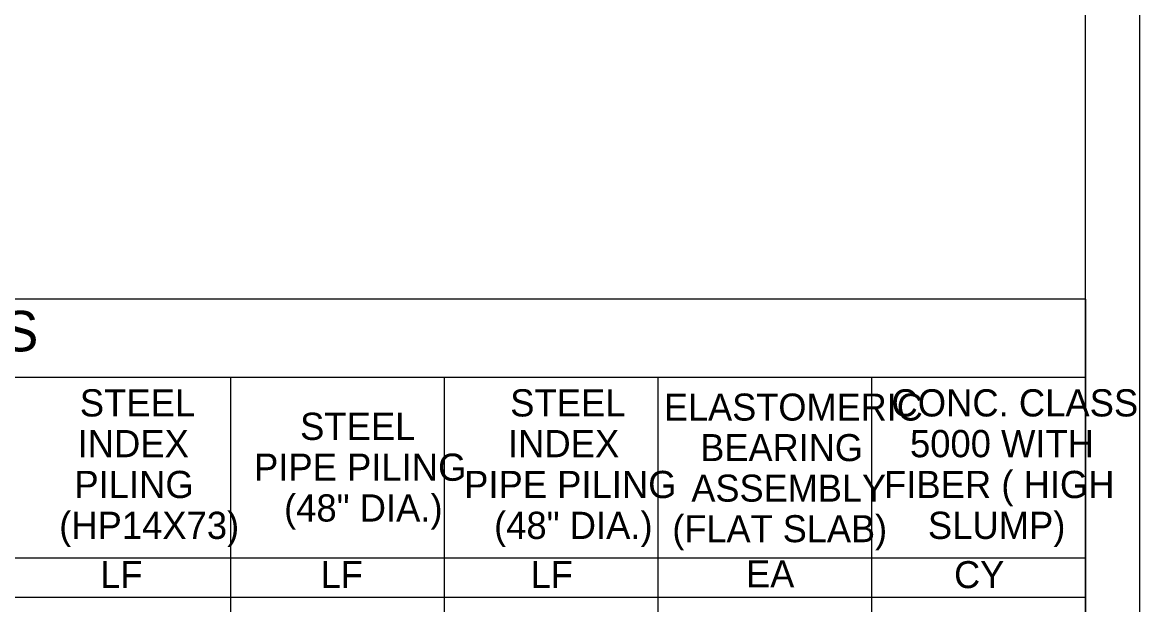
# Model space of a CAD drawing. Extents: x 1334.3 to 1370.4, y 717.9 to 739.9.
# Drawn here: x 1360 to 1370.33, y 723.48 to 728.87 of the extents above; entities that cross this region are included whole.
import ezdxf

# ---------------------------------------------------------------- set-up
doc = ezdxf.new("R2010")
doc.units = 0
for name, color, linetype in [('BR_BORDER LINES', 7, 'Continuous'), ('BR_TABLE LINES', 7, 'Continuous'), ('BR_TEXT', 7, 'Continuous'), ('RD_SHT_IplotShp', 7, 'Continuous')]:
    doc.layers.add(name, color=color, linetype=linetype)

msp = doc.modelspace()

# ---------------------------------------------------------------- linework, layer by layer
at = {"layer": 'BR_BORDER LINES'}
for p, q in [((1369.834, 718.365), (1369.834, 739.365)), ((1369.834, 726.305), (1336.167, 726.305)), ((1369.834, 726.305), (1369.834, 721.363)), ((1369.834, 725.579), (1336.167, 725.579))]:
    msp.add_line(p, q, dxfattribs=at)
at = {"layer": 'BR_TABLE LINES'}
for p, q in [((1361.921, 725.579), (1361.921, 721.363)), ((1363.899, 725.579), (1363.899, 721.363)), ((1365.877, 725.579), (1365.877, 721.363)), ((1367.854, 725.579), (1367.854, 721.363)), ((1369.834, 723.91), (1345.152, 723.91)), ((1369.834, 723.546), (1345.152, 723.546))]:
    msp.add_line(p, q, dxfattribs=at)
at = {"layer": 'RD_SHT_IplotShp'}
msp.add_lwpolyline([(1334.334, 739.865), (1370.334, 739.865), (1370.334, 717.865), (1334.334, 717.865)], close=True, dxfattribs=at)

# ---------------------------------------------------------------- texts
at = {"layer": 'BR_TEXT'}
for s, height, p in [('TABULATION OF ESTIMATED BRIDGE QUANTITIES', 0.375, (1347.941, 725.822)), ('STEEL', 0.2518, (1360.528, 725.22)), ('STEEL', 0.2518, (1364.51, 725.22)), ('ELASTOMERIC', 0.25, (1365.932, 725.182)), ('CONC. CLASS', 0.25178, (1368.038, 725.22)), ('STEEL', 0.2518, (1362.566, 725.003)), ('INDEX', 0.2518, (1360.508, 724.843)), ('INDEX', 0.2518, (1364.49, 724.843)), ('5000 WITH', 0.2518, (1368.209, 724.843)), ('BEARING', 0.25, (1366.269, 724.807)), ('PIPE PILING ', 0.25178, (1362.14, 724.625)), ('PILING ', 0.2518, (1360.478, 724.465)), ('PIPE PILING ', 0.25178, (1364.084, 724.465)), ('ASSEMBLY', 0.25, (1366.186, 724.432)), ('FIBER ( HIGH', 0.25178, (1367.969, 724.465)), ('(48" DIA.)', 0.2518, (1362.418, 724.248)), ('(HP14X73)', 0.2518, (1360.337, 724.087)), ('(48" DIA.)', 0.2518, (1364.361, 724.087)), ('(FLAT SLAB)', 0.25, (1366.01, 724.057)), ('SLUMP)', 0.2518, (1368.375, 724.087)), ('LF', 0.25, (1360.717, 723.632)), ('LF', 0.25, (1362.756, 723.632)), ('LF', 0.25, (1364.7, 723.632)), ('EA', 0.25, (1366.693, 723.639)), ('CY', 0.25, (1368.617, 723.632))]:
    msp.add_text(s, height=height, dxfattribs=at).set_placement(p)

doc.saveas('drawing.dxf')
